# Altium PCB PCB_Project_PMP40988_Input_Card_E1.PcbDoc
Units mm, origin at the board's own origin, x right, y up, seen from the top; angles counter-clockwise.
Board outline 25 x 35.6 mm, 2 copper layers (Top Layer, Bottom Layer), stack 1.646 mm thick; 6 components, 3 nets, 12 pads, 175 vias.
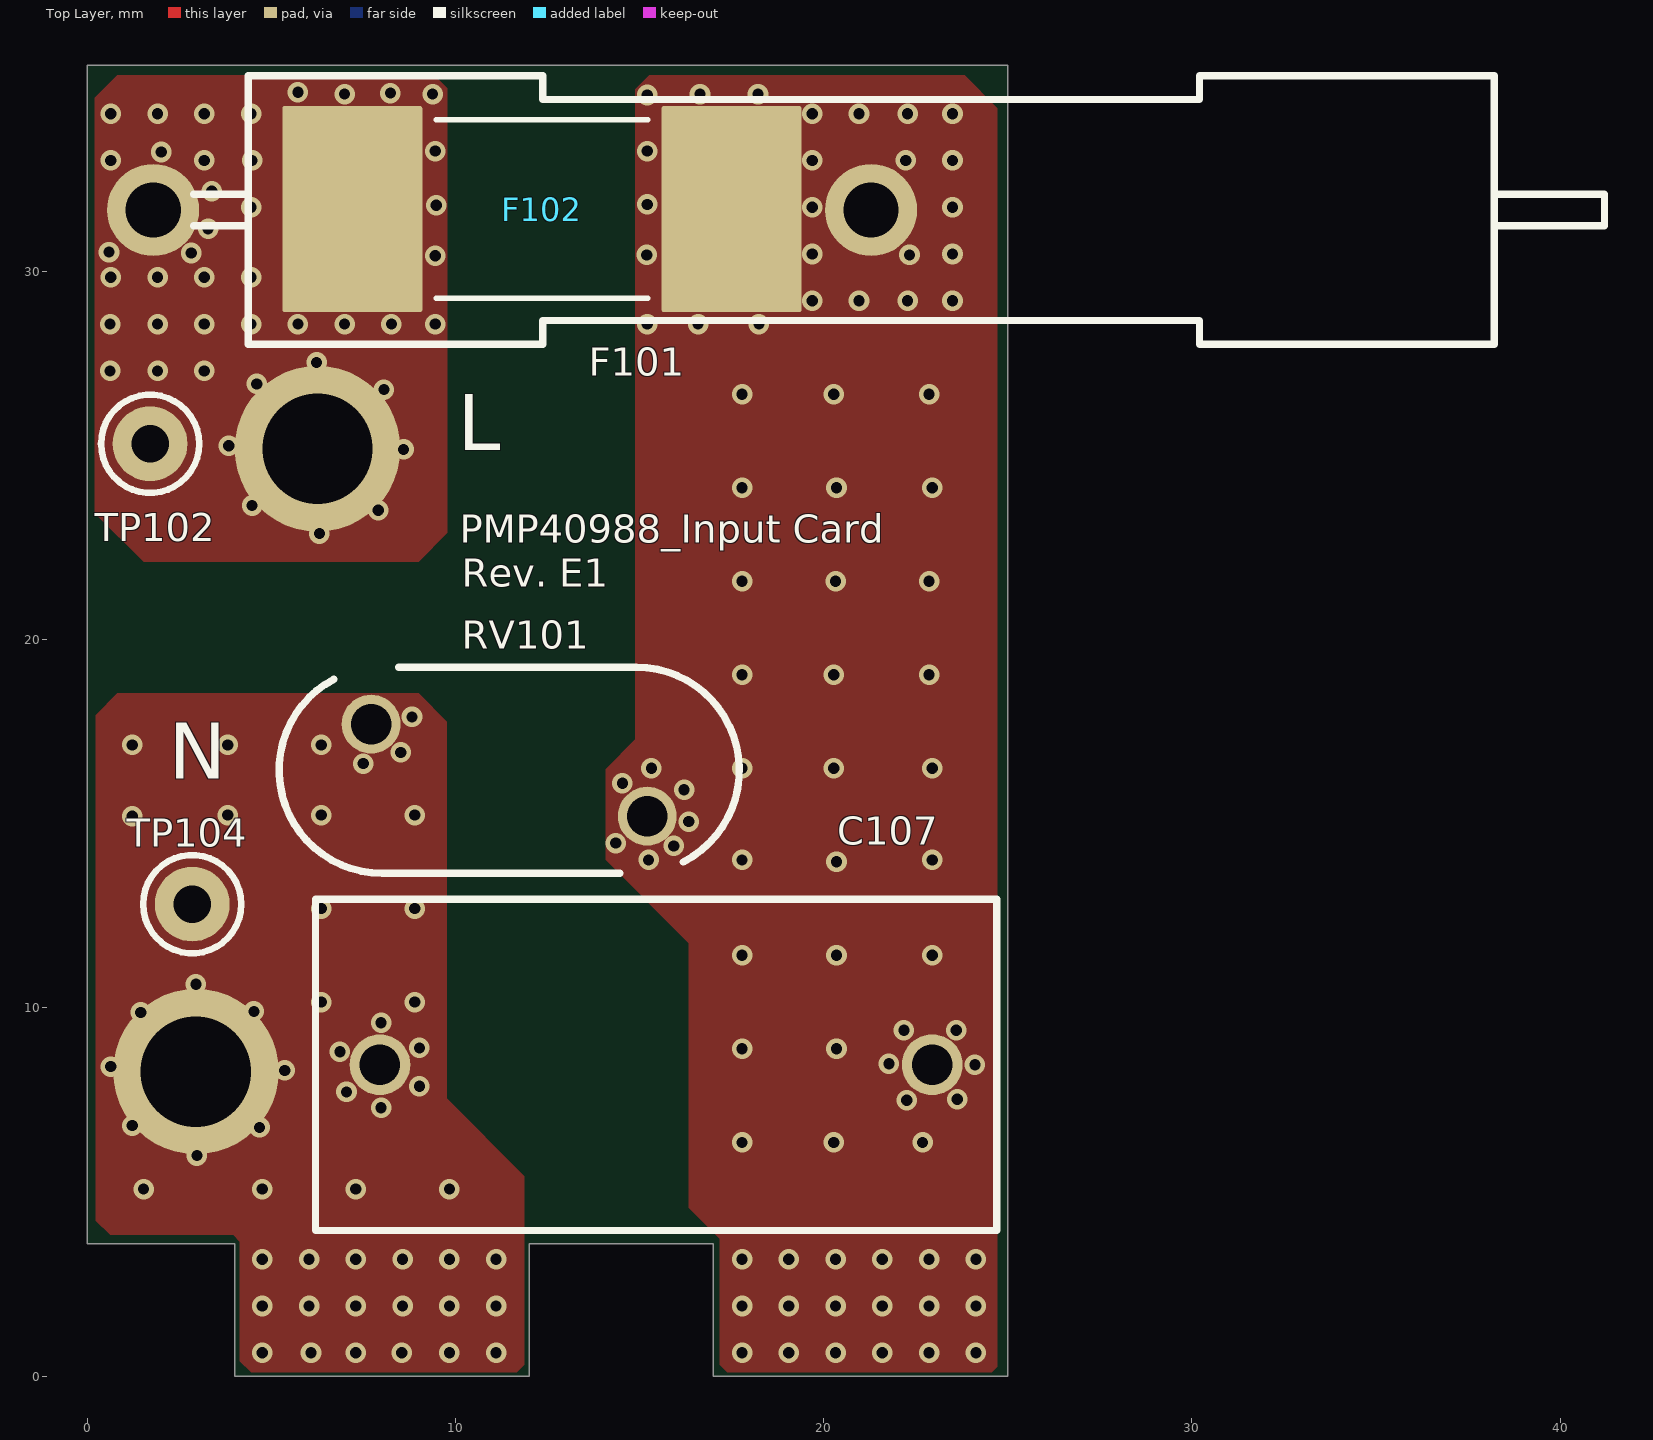
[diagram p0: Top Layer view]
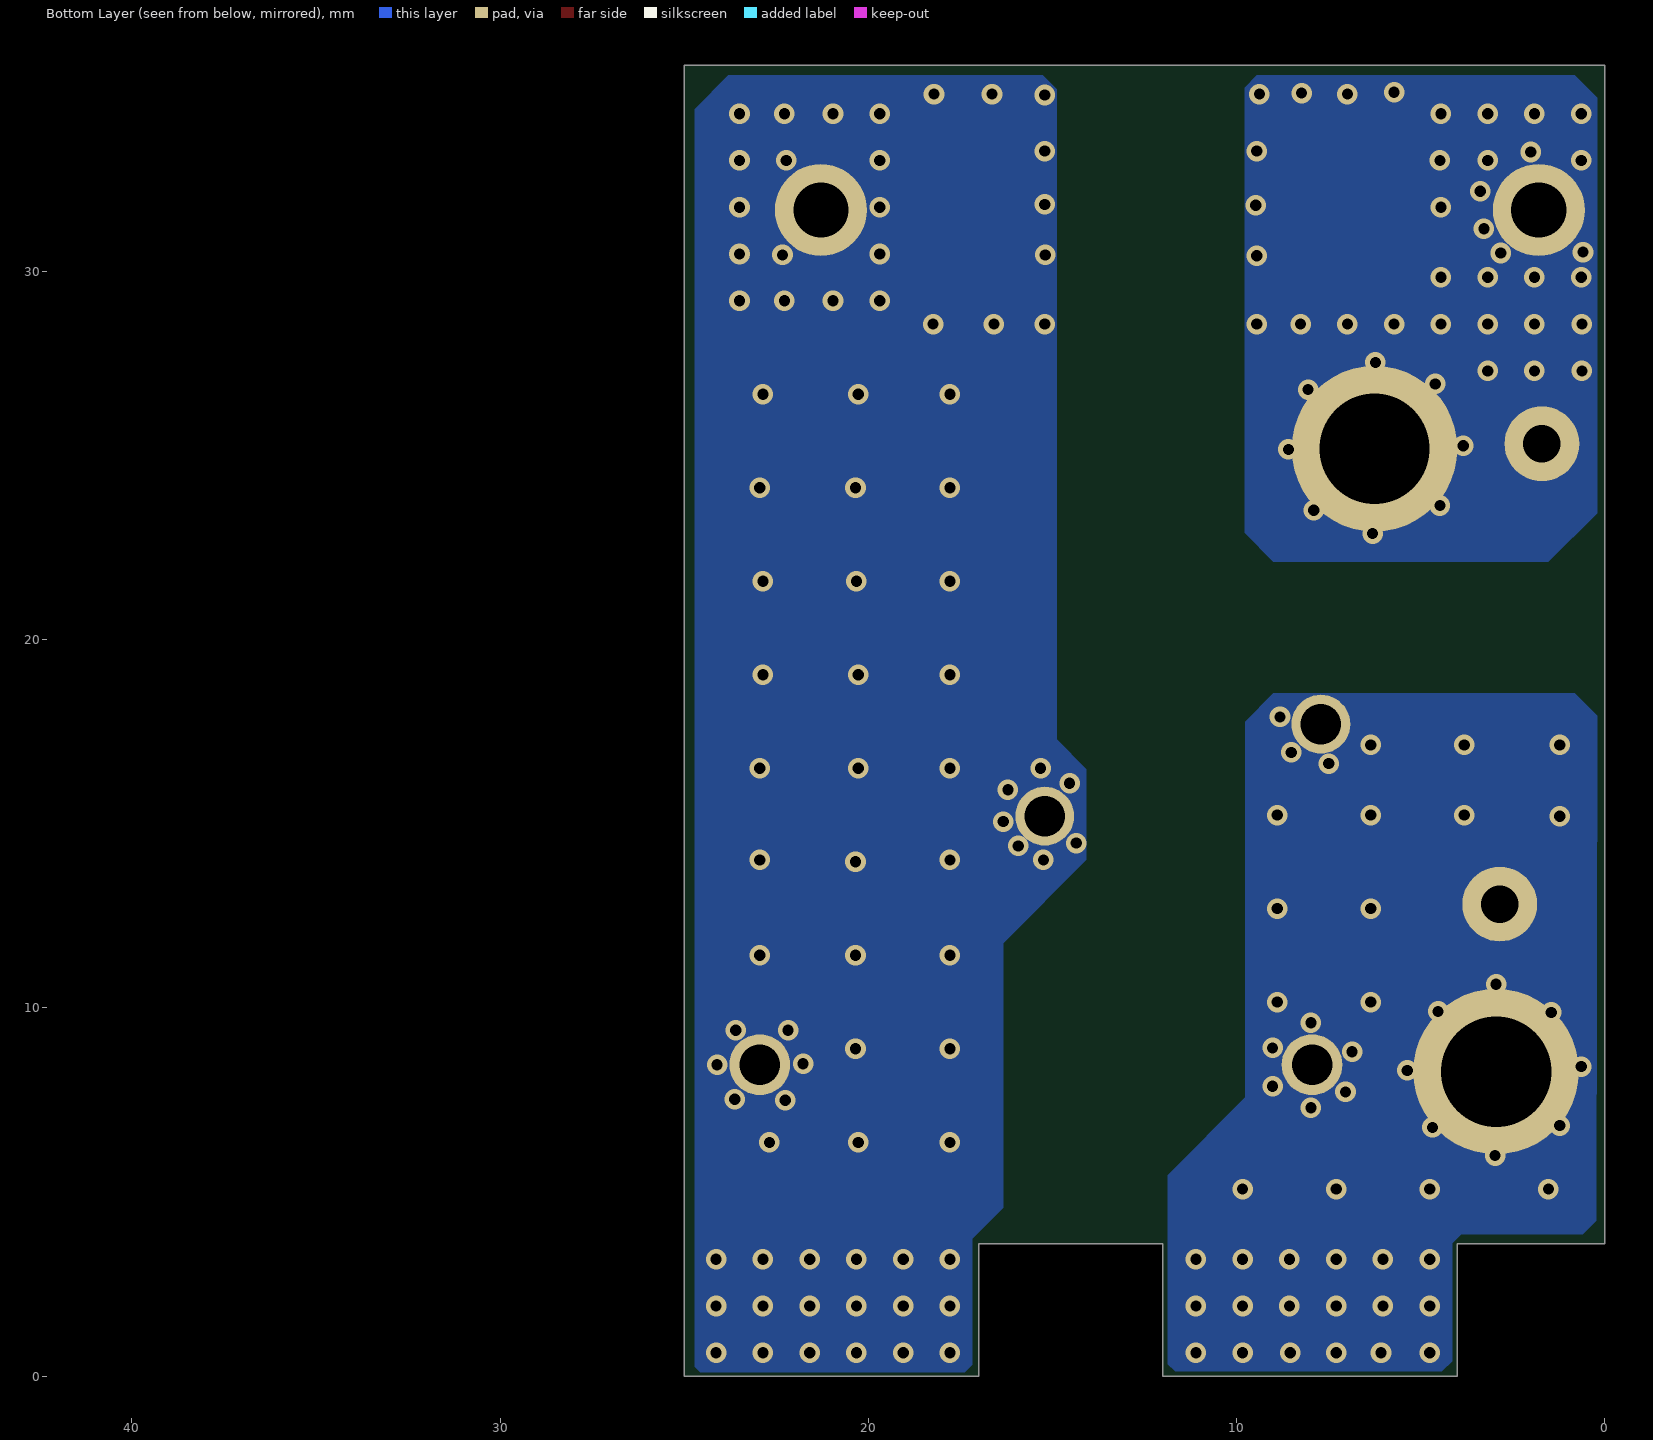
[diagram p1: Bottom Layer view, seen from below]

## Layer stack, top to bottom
Top Solder: solder mask 0.0102, Solder Resist, Dk 3.5
Top Layer: signal copper 0.0711
Dielectric1: core 1.5037, FR-4 High Tg, Dk 4.8
Bottom Layer: signal copper 0.0711
Bottom Solder: solder mask 0.0102, Solder Resist, Dk 3.5

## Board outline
4,0 4,3.6 0,3.6 0,35.6 25,35.6 25,0 17,0 17,3.6 12,3.6 12,0

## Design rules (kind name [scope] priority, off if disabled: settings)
AcuteAngle [All] p1: minimum=4.50000000000000E+0001 checktracksonly=FALSE
AssemblyTestPointUsage [All] p1: valid=2
Clearance Clearance_3 [InNet('EARTH') vs Not InNet('EARTH') And Not InNet('12VS')] p1: gap=5.08 ignorepadtopadclearanceinfootprint=FALSE except(0: Arc-Hole Track-Hole SMDPad-Hole THPad-Hole Via-Hole Fill-Hole Poly-Hole Region-Hole Text-Hole)
Clearance Clearance_1 [InNetClass('HV') vs InNetClass('MV')] p2: gap=0.635 ignorepadtopadclearanceinfootprint=FALSE except(0: Arc-Hole Track-Hole SMDPad-Hole THPad-Hole Via-Hole Fill-Hole Poly-Hole Region-Hole Text-Hole)
Clearance Clearance_2 [InNetClass('HV') vs Not InNetClass('HV')] p3: gap=1.27 ignorepadtopadclearanceinfootprint=FALSE except(0: Arc-Hole Track-Hole SMDPad-Hole THPad-Hole Via-Hole Fill-Hole Poly-Hole Region-Hole Text-Hole)
Clearance Clearance_Keepouts [((IsTrack Or IsArc) And Not InPoly) And IsFree and IsKeepOut vs ((IsTrack Or IsArc) And Not InPoly) And IsFree and IsKeepOut] p4: gap=0 ignorepadtopadclearanceinfootprint=FALSE
Clearance Clearance_BoardEdge_MountingHoles [OnCopper and InComponentClass('Mounting Holes') vs IsKeepOut] p5: gap=1.016 ignorepadtopadclearanceinfootprint=FALSE except(0: Arc-Hole Track-Hole SMDPad-Hole THPad-Hole Via-Hole Fill-Hole Poly-Hole Region-Hole Text-Hole)
Clearance Clearance_BoardEdge_Poly [OnCopper and InPoly vs IsKeepOut] p6: gap=0.635 ignorepadtopadclearanceinfootprint=FALSE except(0: Arc-Hole Track-Hole SMDPad-Hole THPad-Hole Via-Hole Fill-Hole Poly-Hole Region-Hole Text-Hole)
Clearance Clearance_BoardEdge [OnCopper and Not InComponentClass('Logo') and not InComponentClass('FiducialMark') and not InRegion(1000,500,4000,800) and Not IsKeepout vs IsKeepOut] p7: gap=1.905 ignorepadtopadclearanceinfootprint=FALSE except(0: Arc-Hole Track-Hole SMDPad-Hole THPad-Hole Via-Hole Fill-Hole Poly-Hole Region-Hole Text-Hole)
Clearance Clearance_Poly [InPolygon] p8: gap=0.254 ignorepadtopadclearanceinfootprint=FALSE except(0: Arc-Hole Track-Hole SMDPad-Hole THPad-Hole Via-Hole Fill-Hole Poly-Hole Region-Hole Text-Hole)
Clearance [All] p9: gap=0.2 ignorepadtopadclearanceinfootprint=FALSE except(0: Arc-Hole Track-Hole SMDPad-Hole THPad-Hole Via-Hole Fill-Hole Poly-Hole Region-Hole Text-Hole)
ComponentClearance ComponentClearance_MountingHoles_FiducialMarks [InComponentClass('Mounting Holes') vs InComponentClass('FiducialMark')] p1: gap=0.508 collisioncheckmode=3 verticalgap=0.254 showdistances=FALSE
ComponentClearance ComponentClearance_Shunt [InComponentClass('Header') vs InComponentClass('Shunt')] p2: gap=0 collisioncheckmode=3 verticalgap=0 showdistances=FALSE
ComponentClearance ComponentClearance_Logo [InComponentClass('Logo')] p3: gap=0.127 collisioncheckmode=3 verticalgap=0.254 showdistances=FALSE
ComponentClearance ComponentClearance_ScrewToNut [(HasFootprint('NY PMS 440 0025 PH')) vs (HasFootprint('Keystone_1902C'))] p4: gap=0.508 collisioncheckmode=3 verticalgap=2540 showdistances=FALSE
ComponentClearance ComponentClearance_MountingHoles [InComponentClass('Mounting Holes')] p5: gap=0.508 collisioncheckmode=3 verticalgap=0.254 showdistances=FALSE
ComponentClearance ComponentClearance_SmallPassives [HasFootprint('0201*') or HasFootprint('0402*') or HasFootprint('0508') or HasFootprint('0603*') or HasFootprint('0612') or HasFootprint('0805*') or HasFootprint('0815*') or HasFootprint('0830*') or HasFootprint('1206*') or HasFootprint('1210*') or HasFootprint('1808*') or HasFootprint('1812*') or HasFootprint('1825*') or HasFootprint('2010*') or HasFootprint('2220*') or HasFootprint('2225*') or HasFootprint('2512*') or HasFootprint('2728*') or HasFootprint('3518*') vs HasFootprint('0201*') or HasFootprint('0402*') or HasFootprint('0508') or HasFootprint('0603*') or HasFootprint('0612') or HasFootprint('0805*') or HasFootprint('0815*') or HasFootprint('0830*') or HasFootprint('1206*') or HasFootprint('1210*') or HasFootprint('1808*') or HasFootprint('1812*') or HasFootprint('1825*') or HasFootprint('2010*') or HasFootprint('2220*') or HasFootprint('2225*') or HasFootprint('2512*') or HasFootprint('2728*') or HasFootprint('3518*')] p6: gap=0.508 collisioncheckmode=3 verticalgap=0.508 showdistances=FALSE
ComponentClearance ComponentClearance_THtoSMT [IsThruComponent vs IsSMTComponent] p7: gap=0.254 collisioncheckmode=3 verticalgap=0.254 showdistances=FALSE
ComponentClearance ComponentClearance_THtoTH [IsThruComponent vs IsThruComponent] p8: gap=0.254 collisioncheckmode=3 verticalgap=0.254 showdistances=FALSE
ComponentClearance [All] p9: gap=0.254 collisioncheckmode=3 verticalgap=0.254 showdistances=FALSE
DiffPairsRouting [All] p1: maxlimit=2.54 minlimit=0.254 mostfreqgap=0.254 toplayer_minwidth=0.381 toplayer_maxwidth=0.381 toplayer_prefwidth=0.381 bottomlayer_minwidth=0.381 bottomlayer_maxwidth=0.381 bottomlayer_prefwidth=0.381 maxuncoupledlength=25.4
FabricationTestPointUsage TestPointUsage [All] p1: valid=2 allowmultiple=FALSE
FabricationTestpoint Testpoint [All] p1: side=3 testpointundercomponent=TRUE minsize=1.016 maxsize=2.54 preferedsize=1.524 minholesize=0 maxholesize=1.016 preferedholesize=0.813 testpointgrid=0.025 allowsidetop=TRUE allowsidebottom=TRUE usegrid=TRUE gridtolerance=0
FanoutControl Fanout_LCC [IsLCC] p1: bgadir=Out bgaviamode=Centered fanoutstyle=Auto fanoutdirection=Alternating viagrid=0.025 // Fanout_LCC (Default Rule)
FanoutControl Fanout_BGA [IsBGA] p2: bgadir=Out bgaviamode=Centered fanoutstyle=Auto fanoutdirection=Alternating viagrid=0.025 // Fanout_BGA (Default Rule)
FanoutControl Fanout_Default [All] p4: bgadir=Out bgaviamode=Centered fanoutstyle=Auto fanoutdirection=Alternating viagrid=0.025 // Fanout_Default (Default Rule)
FanoutControl Fanout_Small [(CompPinCount < 5)] p5: bgadir=Out bgaviamode=Centered fanoutstyle=Auto fanoutdirection=OutThenIn viagrid=0.025 // Fanout_Small (Default Rule)
Height [All] p1: minheight=0 maxheight=76.2 prefheight=12.7
HoleSize [All] p1: absolutevalues=TRUE maxlimit=6.375 minlimit=0.178 maxpercent=80.000 minpercent=20.000
MinimumAnnularRing MinimumAnnularRing_ThermalPadVias [IsVia and InAnyComponent] p1: minimumring=0.15
MinimumAnnularRing [All] p2: minimumring=0.124
MinimumSolderMaskSliver MinimumSolderMaskSliver_Logo [InComponentClass('Logo') vs InComponentClass('Logo')] p1: minsoldermaskwidth=0.018
MinimumSolderMaskSliver [All] p2: minsoldermaskwidth=0.051
PlaneConnect [All] p1: planeconnectstyle=Direct reliefexpansion=0.254 reliefentries=4 reliefconductorwidth=0.254 reliefairgap=0.254
PolygonConnect [All] p1: connectstyle=Direct reliefconductorwidth=0.254 reliefentries=4 polygonreliefangle="90 Angle" airgapwidth=0.254
RoutingVias ThermalPadVias [IsVia and InAnyComponent] p1: holewidth=0.2 width=0.5 viastyle="Through Hole" minholewidth=0.2 minwidth=0.5 maxholewidth=0.33 maxwidth=0.6
RoutingVias [All] p2: holewidth=0.406 width=0.864 viastyle="Through Hole" minholewidth=0.2 minwidth=0.508 maxholewidth=1.016 maxwidth=1.651
SilkToBoardRegionClearance [Not ((IsComment or IsDesignator) And (Hide <> 'False')) and not InRegion(1000,500,4000,800)] p1:
SilkToSilkClearance SilkToSilkClearance_Pb-FreeLogo [(HasFootprint('Pb-Free_Overlay_Medium') OR HasFootprint('Pb-Free_Overlay_Small')) vs (HasFootprint('Pb-Free_Overlay_Medium') OR HasFootprint('Pb-Free_Overlay_Small'))] p1: silktosilkclearance=0
SilkToSilkClearance [All] p2: silktosilkclearance=0.025
SilkToSolderMaskClearance "Silk to Solder Mask Opening" [All] p1: minsilkscreentomaskgap=0.025 clearancetoexposedcopper=FALSE
SolderMaskExpansion [All] p1: expansion=0.05
Width [All] p1: maxlimit=2.54 minlimit=0.152 preferedwidth=0.254 checkconnectedcopper=TRUE
14 further rules are at their usual default settings.

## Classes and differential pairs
net class HV: L_Wire N_Wire NetF101_1

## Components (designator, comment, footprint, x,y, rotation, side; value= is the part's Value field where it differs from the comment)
C107 "330nF" WCAP-FTXX_L18W8.5H14.5 15.443,8.458 r0 top
F101 "0ADEP9300-RE" Fuse_505_MXE 21.285,31.674 r0 top
F102 "0684L9400-01" FP-0684L9400-01_SMD2-MFG 12.344,31.699 r0 top
RV101 "V320LA10P" VAR_LA_320V 11.455,16.459 r0 top value="420 V"
TP102 "L" Keystone5000 1.702,25.324 r90 top value=Red
TP104 "N" Keystone5001 2.845,12.82 r90 top value=Black

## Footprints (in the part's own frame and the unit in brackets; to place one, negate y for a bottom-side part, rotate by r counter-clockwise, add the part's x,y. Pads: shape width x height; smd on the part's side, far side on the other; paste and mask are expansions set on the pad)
FP-0684L9400-01_SMD2-MFG [mm]
  rrect3% 3.8x5.6 smd paste+0 mask+0: 1(-5.15,0) 2(5.15,0)
  silkscreen extent -2.88,-2.42 2.88,2.42, body extent -7.15,-2.9 7.15,2.9, height 0.25
Fuse_505_MXE [mm] "TH, 2-Leads, Dia 6.985mm, Axial, Pin Spacing 39mm"
  round 2.5 hole 1.5: 1(-19.5,0) 2(0,0)
  silkscreen extent -18.4,-3.64 19.92,3.64, body extent -20,-3.63 20,3.65, height 10.28
Keystone5000 [mil] "For Keystone 500x miniature loop terminals"
  round 80 hole 40: 1(0,0)
  silkscreen extent -52,-52 52,52, body extent -49,-49 49,49, height 182
Keystone5001 [mil] "For Keystone 500x miniature loop terminals"
  round 80 hole 40: 1(0,0)
  silkscreen extent -52,-52 52,52, body extent -49,-49 49,49, height 182
VAR_LA_320V [mm] "Littelfuse, up to 320V"
  round 1.6 hole 1.1: 1(-3.75,1.25) 2(3.75,-1.25)
  silkscreen extent -6.25,-2.8 6.25,2.8, body extent -6.2,-2.78 6.25,2.82, height 17.99
WCAP-FTXX_L18W8.5H14.5 [mm] "Film Capacitors, 18x8.5x14.5mm"
  round 1.65 hole 1.1: 1(-7.5,0) 2(7.5,0)
  silkscreen extent -9.25,-4.5 9.25,4.5, body extent -9,-4.25 9,4.25, height 14.55

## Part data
C107: library part 890334025034, "WCAP-FTXX Film Capacitor, THT, L18W8.5H14.5, 330nF, 310V", Capacitance Tolerance=+/-10%, Insulation Resistance=30000MOhm, Manufacturer="Wurth Elektronik", Operating Temperature="-40 to +105degC", Rated Voltage=310VAC, Rate of Voltage Rise=260V/us
F101: library part CMP-0003520-2, "Fuse, 30 A, 500VAC, TH", Irating_A=30A, Manufacturer="Bel Fuse Inc.", Supplier Part Number 1=507-2105-ND
F102: library part CMP-0092647-1, "40 A 350 V AC DC Fuse Board Mount (Cartridge Style Excluded) Holder Cartridge, Non-Standard", Digikey Part Number=507-2081-1-ND, Fuse Current=40A, Manufacturer="Bel Fuse", Mouser Part Number=530-0684L9400-01, Operating Temperature Range="-55°C to +125°C"
RV101: library part CMP-0002098-2, "Varistor, 420 V, TH", Manufacturer=Littelfuse, Supplier Part Number 1=F1952-ND
TP102: library part 5000, "Test Point, Miniature, Red, TH", Manufacturer=Keystone, Supplier Part Number 1=36-5000-ND
TP104: library part 5001, "Test Point, Miniature, Black, TH", Manufacturer=Keystone, Supplier Part Number 1=36-5001-ND

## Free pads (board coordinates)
  round 4.5 hole 3: 1(2.946,8.274) 1(6.248,25.19)

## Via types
v1: diameter 0.559, hole 0.305, Top Layer to Bottom Layer, tented both sides, 175 vias

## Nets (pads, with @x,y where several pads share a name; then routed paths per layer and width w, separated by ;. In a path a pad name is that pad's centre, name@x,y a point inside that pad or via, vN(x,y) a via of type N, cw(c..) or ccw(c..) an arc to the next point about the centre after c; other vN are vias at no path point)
L_Wire: C107.2 F101.2 F102.2 RV101.2
  other v1: 17.78,0.635 19.05,0.635 20.32,0.635 21.59,0.635 22.86,0.635 24.13,0.635 17.78,1.905 19.05,1.905 20.32,1.905 21.59,1.905 22.86,1.905 24.13,1.905 17.78,3.175 19.05,3.175 20.32,3.175 21.59,3.175 22.86,3.175 24.13,3.175 17.78,6.35 20.269,6.35 22.682,6.35 22.25,7.493 23.622,7.518 24.105,8.458 21.768,8.484 17.78,8.89 20.345,8.89 22.174,9.398 23.597,9.398 17.78,11.43 20.345,11.43 22.943,11.43 20.345,13.97 15.24,14.021 17.78,14.021 22.943,14.021 15.926,14.402 14.351,14.478 16.332,15.062 16.205,15.926 14.529,16.104 15.316,16.51 17.78,16.51 20.269,16.51 22.943,16.51 17.78,19.05 20.269,19.05 22.86,19.05 17.78,21.59 20.32,21.59 22.86,21.59 17.78,24.13 20.345,24.13 22.943,24.13 17.78,26.67 20.269,26.67 22.86,26.67 15.205,28.575 16.586,28.575 18.237,28.575 19.685,29.21 20.955,29.21 22.276,29.21 23.495,29.21 15.189,30.455 22.327,30.455 19.685,30.48 23.495,30.48 19.685,31.75 23.495,31.75 15.205,31.826 19.685,33.02 22.225,33.02 23.495,33.02 15.205,33.274 19.685,34.29 20.955,34.29 22.276,34.29 23.495,34.29 15.205,34.798 16.637,34.823 18.212,34.823
N_Wire: C107.1 pad.1@2.946,8.274 RV101.1 TP104.1
  other v1: 4.75,0.635 6.071,0.635 7.29,0.635 8.534,0.635 9.83,0.635 11.1,0.635 4.75,1.905 6.02,1.905 7.29,1.905 8.56,1.905 9.83,1.905 11.1,1.905 4.75,3.175 6.02,3.175 7.29,3.175 8.56,3.175 9.83,3.175 11.1,3.175 1.524,5.08 4.75,5.08 7.29,5.08 9.83,5.08 2.972,5.994 4.674,6.756 1.219,6.807 7.976,7.29 7.036,7.722 9.017,7.874 5.359,8.306 0.635,8.407 6.858,8.814 9.017,8.915 7.976,9.601 1.448,9.881 4.521,9.906 6.35,10.16 8.89,10.16 2.946,10.643 6.35,12.7 8.89,12.7 1.219,15.209 3.81,15.24 6.35,15.24 8.89,15.24 7.493,16.637 8.509,16.942 1.219,17.145 3.81,17.145 6.35,17.145 8.814,17.907
NetF101_1: F101.1 F102.1 pad.1@6.248,25.19 TP102.1
  other v1: 6.299,22.885 7.899,23.52 4.47,23.647 8.585,25.171 3.835,25.273 8.052,26.797 4.597,26.949 0.613,27.305 1.905,27.305 3.175,27.305 6.223,27.534 0.613,28.575 1.905,28.575 3.175,28.575 4.445,28.575 5.715,28.575 6.985,28.575 8.255,28.575 9.449,28.575 0.635,29.845 1.905,29.845 3.175,29.845 4.445,29.845 9.449,30.429 2.819,30.505 0.584,30.531 3.277,31.166 4.445,31.75 9.474,31.801 3.378,32.182 0.635,33.02 3.175,33.02 4.47,33.02 2.007,33.249 9.449,33.274 0.635,34.29 1.905,34.29 3.175,34.29 4.445,34.29 6.985,34.823 9.373,34.823 8.23,34.849 5.715,34.874

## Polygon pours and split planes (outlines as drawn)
NetF101_1 on Top Layer "Top Layer-No Net" (solid, pour order 22): 9.779,27.898 9.779,34.976 9.423,35.331 0.813,35.331 0.203,34.722 0.203,23.444 1.524,22.123 8.992,22.123 9.779,22.911
N_Wire on Top Layer "Top Layer-No Net 2" (solid, pour order 16): 9.754,7.544 11.862,5.436 11.862,0.305 11.659,0.102 4.445,0.102 4.14,0.406 4.14,0.61 4.14,3.658 3.962,3.835 0.613,3.835 0.229,4.22 0.229,17.958 0.813,18.542 8.992,18.542 9.754,17.78
L_Wire on Top Layer "Top Layer-No Net 1" (solid, pour order 14): 15.265,35.331 14.884,34.95 14.884,28.534 14.884,17.297 14.072,16.485 14.072,14.021 16.332,11.76 16.332,4.572 17.17,3.734 17.17,0.305 17.374,0.102 24.562,0.102 24.714,0.254 24.714,34.442 23.825,35.331
NetF101_1 on Bottom Layer "Top Layer-No Net" (solid, pour order 24): 9.779,27.898 9.779,35.001 9.449,35.331 0.813,35.331 0.203,34.722 0.203,23.444 1.524,22.123 8.992,22.123 9.779,22.911
L_Wire on Bottom Layer "Top Layer-No Net 1" (solid, pour order 20): 24.714,34.417 23.8,35.331 15.265,35.331 14.884,34.95 14.884,17.297 14.072,16.485 14.072,14.021 16.332,11.76 16.332,4.572 17.17,3.734 17.17,0.305 17.374,0.102 24.562,0.102 24.714,0.254
N_Wire on Bottom Layer "Top Layer-No Net 2" (solid, pour order 18): 4.775,0.129 4.418,0.129 4.14,0.406 4.14,3.607 3.886,3.861 0.588,3.861 0.229,4.22 0.203,17.932 0.813,18.542 8.992,18.542 9.754,17.78 9.754,7.569 11.862,5.461 11.862,0.33 11.659,0.127

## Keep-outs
Keep-Out Layer:
  text ".Layer_Name" at -24.003,-44.342 h1.52

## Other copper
Top Layer:
  text ".Layer_Name" at -24.003,-44.342 h1.52
Bottom Layer:
  text ".Layer_Name" at -24.003,-44.342 h1.52

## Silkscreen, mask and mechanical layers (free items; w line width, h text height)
Top Overlay:
  text "L" at 10.058,25.146 h1.52
  text "PMP40988_Input Card" at 10.109,22.631 h0.76
  text "Rev. E1" at 10.16,21.438 h0.76
  text "N" at 2.21,16.231 h1.52
  text ".Layer_Name" at -24.003,-44.342 h1.52
Bottom Overlay:
  text ".Layer_Name" at -24.003,-44.342 h1.52
Top Paste:
  text ".Layer_Name" at -24.003,-44.342 h1.52
Bottom Paste:
  text ".Layer_Name" at -24.003,-44.342 h1.52
Top Solder:
  rectangle: 16.993,0.025 24.994,3.607
  rectangle: 3.988,0.025 11.989,3.607
  text ".Layer_Name" at -24.003,-44.342 h1.52
  text ".Layer_Name" at -24.003,-44.342 h1.52
Bottom Solder:
  rectangle: 16.993,0.025 24.994,3.607
  rectangle: 3.988,0.025 11.989,3.607
  text ".Layer_Name" at -24.003,-44.342 h1.52
Drill Guide:
  text ".Layer_Name" at -24.003,-44.342 h1.52
M1 Board Outline:
  lines w0.178: 0,3.6 0,35.6 25,35.6 25,3.6 25,0 17,0 17,3.6 12,3.6 12,0 4,0 4,3.6 0,3.6
  text ".Layer_Name" at -24.003,-44.342 h1.52
M2 Board Dimensions:
  rectangle: -35.484,-32.697 -25.959,-29.522
  rectangle: -38.659,-29.522 -35.484,-26.347
  lines w0.178: -38.659,-29.522 -13.259,-29.522 ; -35.484,-32.697 -35.484,-26.347 ; -32.309,-32.697 -32.309,-26.347 ; -25.959,-32.697 -25.959,-26.347 ; -19.609,-32.697 -19.609,-26.347 ; -38.659,-32.697 -38.659,-26.347 -13.259,-26.347 -13.259,-32.697 -38.659,-32.697
  text ".Layer_Name" at -24.003,-44.342 h1.52
M3 3D STEP Top:
  text ".Layer_Name" at -24.003,-44.342 h1.52
M4 3D STEP Bottom:
  text ".Layer_Name" at -24.003,-44.342 h1.52
M5 Assembly Top:
  lines w0.254: -46.076,-46.163 121.564,-46.163 ; -46.076,-40.998 121.615,-40.998 ; -46.076,-35.833 -46.076,-51.327 55.651,-51.327 121.615,-51.327 121.615,-35.834 -46.063,-35.834 -46.063,-51.327 -6.045,-51.327 ; 16.535,-51.327 16.535,-35.834 ; 48.717,-40.998 48.717,-35.834 ; 70.053,-40.998 70.053,-35.834 ; 85.852,-51.493 85.852,-46.341
  text "COMPONENTS MARKED 'DNP' SHOULD NOT BE POPULATED." at -9.36,-30.626 h1.52
  text "ASSEMBLY VARIANT:" at -9.373,-33.56 h1.52
  text ".VariantName" at 16.942,-33.56 h1.52
  text "PCB VIEWED FROM TOP SIDE" at -44.463,-39.191 h1.52
  text "BOARD #:" at 18.44,-39.191 h1.52
  text ".PRJ_Number" at 32.296,-39.191 h1.52
  text "REV:" at 53.746,-39.191 h1.52
  text ".PCB_Rev" at 61.151,-39.191 h1.52
  text "SVN REV:" at 75.032,-39.191 h1.52
  text ".VersionControl_RevNumber" at 87.884,-39.191 h1.52
  text "TID #:" at 18.44,-44.355 h1.52
  text ".TID" at 32.296,-44.355 h1.52
  text "PLOT NAME =" at -44.463,-49.571 h1.52
  text ".plot_File_Name" at -24.003,-49.571 h1.52
  text "GENERATED    :" at 18.491,-49.571 h1.52
  text ".Print_Date" at 40.576,-49.571 h1.52
  text ".Print_Time" at 59.093,-49.571 h1.52
  text "TEXAS INSTRUMENTS" at 91.211,-49.571 h1.52
M6 Assembly Bottom:
  lines w0.254: -46.088,-41.011 121.602,-41.011 ; -46.038,-46.176 121.602,-46.176 ; -10.325,-51.505 -10.325,-46.353 ; 5.474,-41.011 5.474,-35.846 ; 26.81,-41.011 26.81,-35.846 ; 58.991,-51.34 58.991,-35.846 ; 81.572,-51.34 121.59,-51.34 121.59,-35.846 -46.088,-35.846 -46.088,-51.34 19.875,-51.34 121.602,-51.34 121.602,-35.846
  text "COMPONENTS MARKED 'DNP' SHOULD NOT BE POPULATED." at 116.332,-30.614 h1.52
  text ".VariantName" at 89.814,-33.56 h1.52
  text "ASSEMBLY VARIANT:" at 116.205,-33.56 h1.52
  text ".VersionControl_RevNumber" at -12.357,-39.203 h1.52
  text "SVN REV:" at 0.495,-39.203 h1.52
  text ".PCB_Rev" at 14.376,-39.203 h1.52
  text "REV:" at 21.78,-39.203 h1.52
  text ".PRJ_Number" at 43.231,-39.203 h1.52
  text "BOARD #:" at 57.087,-39.203 h1.52
  text "PCB VIEWED FROM BOTTOM SIDE" at 119.99,-39.203 h1.52
  text ".TID" at 43.231,-44.368 h1.52
  text "TID #:" at 57.087,-44.368 h1.52
  text "TEXAS INSTRUMENTS" at -15.684,-49.583 h1.52
  text ".Print_Time" at 16.434,-49.583 h1.52
  text ".Print_Date" at 34.95,-49.583 h1.52
  text "GENERATED    :" at 57.036,-49.583 h1.52
  text ".plot_File_Name" at 99.53,-49.583 h1.52
  text "PLOT NAME =" at 119.99,-49.583 h1.52
M9 Title Sheet:
  drawing of 57 lines, arcs and shapes, not listed
  text "1" at -19.867,181.591 h1.78
  text "2" at 43.523,181.591 h1.78
  text "3" at 106.752,181.591 h1.78
  text "4" at 170.422,181.591 h1.78
  text "5" at 233.896,181.591 h1.78
  text "6" at 297.523,181.591 h1.78
  text "A" at -49.238,152.558 h1.78
  text "A" at 326.682,152.558 h1.78
  text "B" at -49.238,92.106 h1.78
  text "B" at 326.682,92.106 h1.78
  text "C" at -49.238,31.781 h1.78
  text "C" at 326.682,31.781 h1.78
  text "PROJECT TITLE:" at 249.466,-15.488 h1.14
  text ".PRJ_Title" at 250.736,-18.875 h1.78
  text "DESIGNED FOR:" at 249.466,-23.133 h1.14
  text ".PRJ_Customer" at 250.736,-26.689 h1.78
  text "D" at -49.238,-28.417 h1.78
  text "D" at 326.682,-28.417 h1.78
  text "FILE NAME:" at 249.466,-30.753 h1.14
  text ".PCB_File_Name_No_Path" at 250.736,-33.801 h1.78
  text "Texas Instruments (TI) and/or its licensors do not warrant the accuracy or completeness of this specification" at 123.241,-37.912 h1.14
  text "ENGINEER:" at 249.466,-38.119 h1.14
  text "LAYOUT BY:" at 287.693,-38.119 h1.14
  text "or any information contained therein. TI and/or its licensors do not warrant that this design will meet" at 122.098,-40.774 h1.14
  text ".PRJ_Engineer" at 250.736,-42.056 h1.78
  text ".PCB_Layout" at 288.976,-42.056 h1.78
  text "the specifications, will be suitable for your application or fit for any particular purpose, or will operate in" at 122.098,-43.636 h1.14
  text ".Layer_Name" at -24.003,-44.342 h1.52
  text "ALTIUM DESIGNER VERSION:" at 287.693,-45.993 h1.14
  text "an implementation. TI and/or its licensors do not warrant that the design is production worthy. You should" at 122.098,-46.497 h1.14
  text "completely validate and test your design implementation to confirm the system functionality for your application." at 123.241,-49.359 h1.14
  text ".print_Scale" at 250.736,-49.38 h1.78
  text ".Application_BuildNumber" at 288.976,-49.38 h1.78
  text "1" at -19.867,-54.629 h1.78
  text "2" at 43.523,-54.629 h1.78
  text "3" at 106.752,-54.629 h1.78
  text "4" at 170.422,-54.629 h1.78
  text "5" at 233.896,-54.629 h1.78
  text "6" at 297.523,-54.629 h1.78
M10 Fab Notes:
  drawing of 189 lines, arcs and shapes, not listed
  text "DESIGN INFORMATION" at 275.844,138.91 h1.52
  text "MIN. TRACK WIDTH:" at 259.473,135.554 h1.52
  text "8" at 287.317,135.554 h1.52
  text "MIL" at 291.248,135.554 h1.52
  text "7.874" at 283.091,132.463 h1.52
  text "MIN. CLEARANCE:" at 259.473,132.401 h1.52
  text "MIL" at 291.248,132.401 h1.52
  text "MIN. VIA PAD SIZE:" at 259.473,129.249 h1.52
  text "24" at 286.555,129.249 h1.52
  text "MIL" at 291.248,129.249 h1.52
  text "0.05mm (2MIL)" at 277.126,125.949 h1.52
  text "MINIMUM ANNULAR RING" at 251.11,125.74 h1.52
  text "EXTERNAL" at 295.109,125.74 h1.52
  text "PER" at 256.19,122.943 h1.52
  text "IPC-D-275 CLASS 2 LEVEL C" at 261.778,122.943 h1.52
  text "MIL, HOLES" at 299.579,120.391 h1.52
  text "+/-" at 289.611,120.173 h1.52
  text "+/-" at 311.302,120.173 h1.52
  text "REGISTRATION TOLERANCES:" at 251.11,120.146 h1.52
  text "METAL" at 281.584,120.146 h1.52
  text "5" at 296.22,120.146 h1.52
  text "3" at 317.378,120.146 h1.52
  text "MIL" at 320.331,120.146 h1.52
  text "HOLE SIZE TOLERANCE (UNLESS OTHERWISE SPECIFIED):" at 251.11,117.649 h1.52
  text "+/-" at 311.302,117.576 h1.52
  text "3" at 317.378,117.549 h1.52
  text "MIL" at 320.331,117.549 h1.52
  text "MATERIAL:" at 249.211,114.052 h1.52
  text "FR-4 High Tg" at 274.267,110.788 h1.52
  text "X" at 270.598,110.585 h1.52
  text "FR-408" at 259.905,110.47 h1.52
  text "OTHER" at 297.7,110.47 h1.52
  text "62 MIL (1.6mm) +/-10%" at 268.035,106.837 h1.52
  text "X" at 264.985,106.775 h1.52
  text "THICKNESS:" at 251.11,106.628 h1.52
  text "OTHER" at 300.671,106.628 h1.52
  text "TOLERANCE:" at 251.11,103.115 h1.52
  text "X" at 272.655,103.115 h1.52
  text "ANSI IPC-6012 TYPE 3 CLASS 2" at 277.177,103.115 h1.52
  text "OTHER +/-" at 277.176,99.453 h1.52
  text "BOW & TWIST:" at 251.11,95.765 h1.52
  text "X" at 272.655,95.765 h1.52
  text "ANSI IPC-6012 TYPE 3 CLASS 2" at 277.177,95.765 h1.52
  text "OTHER +/-" at 277.176,92.039 h1.52
  text "DRILLING:" at 249.211,88.721 h1.52
  text "NC_DRILL FILES" at 293.94,86.049 h1.52
  text "REFERENCE:" at 251.11,85.949 h1.52
  text "X" at 267.804,85.947 h1.52
  text "AS SHOWN" at 272.325,85.949 h1.52
  text "X" at 290.689,85.949 h1.52
  text "OTHER" at 301.51,82.336 h1.52
  text "PTH COPPER THICKNESS:" at 251.102,82.247 h1.52
  text "X" at 280.039,82.247 h1.52
  text "20-30 um" at 283.29,82.247 h1.52
  text "BOARD FINISH:" at 249.211,78.498 h1.52
  text "SILKSCREEN:" at 253.154,75.7 h1.52
  text "X" at 277.481,75.7 h1.52
  text "TOP" at 280.453,75.7 h1.52
  text "X" at 290.435,75.7 h1.52
  text "BOTTOM" at 293.432,75.7 h1.52
  text "SILKSCREEN COLOR:" at 253.154,71.759 h1.52
  text "X" at 277.456,71.759 h1.52
  text "WHITE" at 280.453,71.759 h1.52
  text "OTHER" at 293.432,71.759 h1.52
  text "X" at 280.783,68.115 h1.52
  text "GREEN" at 283.78,68.115 h1.52
  text "OTHER" at 299.478,68.115 h1.52
  text "SOLDER RESIST COLOR:" at 253.154,67.941 h1.52
  text "X" at 280.783,64.197 h1.52
  text "MATTE" at 283.78,64.197 h1.52
  text "SEMI-GLOSS" at 299.466,64.181 h1.52
  text "IMMERSION GOLD (ENIG)" at 276.16,59.809 h1.52
  text "ENEPIG" at 310.134,59.625 h1.52
  text "SURFACE FINISH:" at 249.211,59.6 h1.52
  text "X" at 271.639,59.6 h1.52
  text "IMM. TIN/SILVER OR EQUIV" at 257.581,56.112 h1.52
  text "OTHER" at 293.94,56.012 h1.52
  text "ARRAY/PANEL:" at 249.211,52.065 h1.52
  text "CUT AND TRIM PER M1 BOARD OUTLINE" at 276.16,51.857 h1.52
  text "N.C. ROUTE" at 276.16,48.403 h1.52
  text "X" at 293.636,48.403 h1.52
  text "V. SCORE" at 298.157,48.403 h1.52
  text "CERTIFICATION:" at 249.211,45.123 h1.52
  text "MATERIALS AND WORKMANSHIP FOR ALL PCBS" at 267.626,45.123 h1.52
  text "TO MEET OR EXCEED THE REQUIREMENTS OF:" at 267.626,42.734 h1.52
  text "X" at 258.419,39.467 h1.52
  text "ANSI IPC-A-600F CLASS ->" at 261.67,39.467 h1.52
  text "X" at 303.529,39.467 h1.52
  text "2" at 306.323,39.467 h1.52
  text "1" at 298.322,39.429 h1.52
  text "3" at 315.315,39.429 h1.52
  text "X" at 279.044,35.716 h1.52
  text "RoHS" at 282.295,35.716 h1.52
  text "OTHER" at 298.662,35.716 h1.52
  text "PER ORDER" at 308.748,35.716 h1.52
  text "ALL BOARDS MUST MEET OR EXCEED UL94-V0 REQUIREMENTS." at 249.911,31.808 h1.52
  text "PCB MUST BEAR THE UL94V-0 UL REGISTERED MATERIAL ID NUMBER" at 249.911,28.86 h1.52
  text "ADDITIONAL REQUIREMENTS:" at 249.211,24.557 h1.52
  text "MICROSECTION:" at 251.11,21.836 h1.52
  text "YES" at 274.116,21.836 h1.52
  text "REQUIRED" at 295.998,18.17 h1.52
  text "BARE BOARD ELEC. TEST:" at 251.11,18.097 h1.52
  text "NONE" at 284.276,18.097 h1.52
  text "X" at 293.001,18.097 h1.52
  text "PER ORDER" at 311.035,18.097 h1.52
  text "XX MIL VIAS REQUIRE NON-CONDUCTIVE FILL AND PLANARIZE" at 255.381,12.892 h1.5
  text "XX MIL VIAS REQUIRE CONDUCTIVE FILL AND PLANARIZE" at 255.584,10.251 h1.52
  text "OUTER XX MIL TRACES REQUIRE 50 OHM SINGLE-ENDED IMPEDANCE" at 255.559,6.101 h1.47
  text "LAYER 2 & 3 (INNER LAYERS) XX MIL WIDE, XX MIL SPACE / TRACES REQUIRE 100 OHM DIFFERENTIAL IMPEDANCE" at 255.356,0.114 h1.52
  text ".Layer_Name" at -24.003,-44.342 h1.52
M11 Gerber Information:
  lines w0.254: -46.076,-46.163 121.564,-46.163 ; -46.076,-40.998 121.615,-40.998 ; -46.076,-35.833 -46.076,-51.327 55.651,-51.327 121.615,-51.327 121.615,-35.834 -46.063,-35.834 -46.063,-51.327 -6.045,-51.327 ; 16.535,-51.327 16.535,-35.834 ; 48.717,-40.998 48.717,-35.834 ; 70.053,-40.998 70.053,-35.834 ; 85.852,-51.493 85.852,-46.341
  text "ALL ARTWORK VIEWED FROM TOP SIDE" at -44.463,-39.191 h1.52
  text "BOARD #:" at 18.44,-39.191 h1.52
  text ".PRJ_Number" at 32.296,-39.191 h1.52
  text "REV:" at 53.746,-39.191 h1.52
  text ".PCB_Rev" at 61.151,-39.191 h1.52
  text "SVN REV:" at 75.032,-39.191 h1.52
  text ".VersionControl_RevNumber" at 87.884,-39.191 h1.52
  text "LAYER NAME =" at -44.463,-44.342 h1.52
  text "TID #:" at 18.44,-44.355 h1.52
  text ".TID" at 32.296,-44.355 h1.52
  text "PLOT NAME =" at -44.463,-49.571 h1.52
  text ".plot_File_Name" at -24.003,-49.571 h1.52
  text "GENERATED    :" at 18.491,-49.571 h1.52
  text ".Print_Date" at 40.576,-49.571 h1.52
  text ".Print_Time" at 59.093,-49.571 h1.52
  text "TEXAS INSTRUMENTS" at 91.211,-49.571 h1.52
M12 Stackup:
  drawing of 191 lines, arcs and shapes, not listed
  text "Layer" at 210.556,176.915 h1.52
  text "Name" at 220.967,176.915 h1.52
  text "Material" at 244.583,176.915 h1.52
  text "Thickness" at 266.421,176.915 h1.52
  text "Constant" at 282.927,176.915 h1.52
  text "Board Layer Stack" at 297.401,176.915 h1.52
  text "1" at 210.556,173.867 h1.52
  text "Top Overlay" at 220.967,173.867 h1.52
  text "2" at 210.556,170.819 h1.52
  text "Top Solder" at 220.967,170.819 h1.52
  text "Solder Resist" at 244.583,170.819 h1.52
  text "0.40mil" at 266.421,170.819 h1.52
  text "3.5" at 282.927,170.819 h1.52
  text "3" at 210.556,167.771 h1.52
  text "Top Layer" at 220.967,167.771 h1.52
  text "Copper" at 244.583,167.771 h1.52
  text "2.80mil" at 266.421,167.771 h1.52
  text "4" at 210.556,164.723 h1.52
  text "Dielectric1" at 220.967,164.723 h1.52
  text "FR-4 High Tg" at 244.583,164.723 h1.52
  text "59.20mil" at 266.421,164.723 h1.52
  text "4.8" at 282.927,164.723 h1.52
  text "5" at 210.556,161.675 h1.52
  text "Bottom Layer" at 220.967,161.675 h1.52
  text "Copper" at 244.583,161.675 h1.52
  text "2.80mil" at 266.421,161.675 h1.52
  text "6" at 210.556,158.627 h1.52
  text "Bottom Solder" at 220.967,158.627 h1.52
  text "Solder Resist" at 244.583,158.627 h1.52
  text "0.40mil" at 266.421,158.627 h1.52
  text "3.5" at 282.927,158.627 h1.52
  text "7" at 210.556,155.579 h1.52
  text "Bottom Overlay" at 220.967,155.579 h1.52
  text ".Layer_Name" at -24.003,-44.342 h1.52
M13 Component Bodies Top:
  text ".Layer_Name" at -24.003,-44.342 h1.52
M14 Component Bodies Bottom:
  text ".Layer_Name" at -24.003,-44.342 h1.52
M15 Courtyards Top:
  text ".Layer_Name" at -24.003,-44.342 h1.52
M16 Courtyards Bottom:
  text ".Layer_Name" at -24.003,-44.342 h1.52
Drill Drawing:
  circle w0.254: c97.58,58.031 r0.702
  lines w0.254: 96.878,47.856 98.281,47.856 98.281,49.26 96.878,49.26 96.878,47.856 ; 96.878,51.365 97.229,51.365 97.229,51.014 97.93,51.014 97.93,51.365 98.281,51.365 98.281,52.067 97.93,52.067 97.93,52.418 97.229,52.418 97.229,52.067 96.878,52.067 96.878,51.365 ; 96.878,55.575 98.281,55.575 97.58,54.172 96.878,55.575 ; 96.878,60.838 97.229,60.838 97.58,60.487 97.93,60.838 98.281,60.838 97.93,61.189 98.281,61.54 97.93,61.54 97.58,61.891 97.229,61.54 96.878,61.54 97.229,61.189 96.878,60.838
  lines w0.305: 95.606,46.909 177.685,46.909 ; 95.606,62.698 177.685,62.698 ; 104.187,43.751 104.187,65.855 ; 112.62,43.751 112.62,65.855 ; 128.789,43.751 128.789,65.855 ; 135.371,43.751 135.371,65.855 ; 144.9,43.751 144.9,65.855 ; 163.298,43.751 163.298,65.855 ; 95.606,43.751 177.685,43.751 177.685,65.855 95.606,65.855 95.606,43.751
  text "Symbol" at 97.5,63.645 h1.83
  text "Quantity" at 105.135,63.645 h1.83
  text "Finished Hole Size" at 113.567,63.645 h1.83
  text "Plated" at 129.736,63.645 h1.83
  text "Hole Type" at 136.318,63.645 h1.83
  text "Drill Layer Pair" at 145.847,63.645 h1.83
  text "Hole Tolerance" at 164.245,63.645 h1.83
  text "175" at 105.135,60.487 h1.52
  text "12.00mil (0.305mm)" at 113.567,60.487 h1.52
  text "PTH" at 129.736,60.487 h1.52
  text "Round" at 136.318,60.487 h1.52
  text "Top Layer - Bottom Layer" at 145.847,60.487 h1.52
  text "2" at 105.135,57.33 h1.52
  text "40.00mil (1.016mm)" at 113.567,57.33 h1.52
  text "PTH" at 129.736,57.33 h1.52
  text "Round" at 136.318,57.33 h1.52
  text "Top Layer - Bottom Layer" at 145.847,57.33 h1.52
  text "4" at 105.135,54.172 h1.52
  text "43.31mil (1.100mm)" at 113.567,54.172 h1.52
  text "PTH" at 129.736,54.172 h1.52
  text "Round" at 136.318,54.172 h1.52
  text "Top Layer - Bottom Layer" at 145.847,54.172 h1.52
  text "2" at 105.135,51.014 h1.52
  text "59.06mil (1.500mm)" at 113.567,51.014 h1.52
  text "PTH" at 129.736,51.014 h1.52
  text "Round" at 136.318,51.014 h1.52
  text "Top Layer - Bottom Layer" at 145.847,51.014 h1.52
  text "2" at 105.135,47.856 h1.52
  text "118.11mil (3.000mm)" at 113.567,47.856 h1.52
  text "PTH" at 129.736,47.856 h1.52
  text "Round" at 136.318,47.856 h1.52
  text "Top Layer - Bottom Layer" at 145.847,47.856 h1.52
  text "185 Total" at 105.135,44.699 h1.52
  text ".Layer_Name" at -24.003,-44.342 h1.52
M17 Embedded Cavity:
  text ".Layer_Name" at -24.003,-44.342 h1.52
M18 Embedded Assembly:
  text ".Layer_Name" at -24.003,-44.342 h1.52
M19 Embedded Keepout:
  text ".Layer_Name" at -24.003,-44.342 h1.52

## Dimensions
0,33.6 to 25,35.6 on M2 Board Dimensions
4,0 to 0,35.6 on M2 Board Dimensions
-38.659,-32.697 to -13.259,-32.697 on M2 Board Dimensions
